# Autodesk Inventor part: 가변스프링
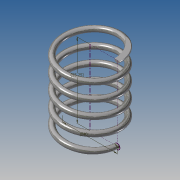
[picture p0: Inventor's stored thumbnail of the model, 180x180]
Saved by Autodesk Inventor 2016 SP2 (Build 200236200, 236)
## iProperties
Created: 2019-03
Part Number: 가변스프링
Material: 스테인레스 스틸
Document SubType Name: Modeling
Designer: EZ
Density: 8 g/cm^3
Appearance: 반연마
Mass: 62.1952 g
Surface Area: 78.8408 cm^2
Volume: 7.7744 cm^3
Author: EZ
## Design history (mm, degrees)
sketch "스케치1"
  geometry: L1 (0, 0)-(20, 0); L2 (20, 0)-(20, 55.251); L3 (20, 55.251)-(0, 55.251); L4 (0, 55.251)-(0, 0); C1 r 2 at (20, 0)
  constraints: 8 end point, 2 parallel, 1 centre point, 1 coincident, 1 horizontal, 1 perpendicular
  dimensions: "d0" = 4 diameter of C1; "d2" = 40 diameter of L2 L4; "d16" = 55.2509 distance between parallel lines of L1 L3 (derived)
feature "코일1" sketch "스케치1" pitch "d4" = 10; turns "d6" = 5; dims "d5" = 55.25091 (= d3), "d7" = 0, angle "d8" = 90 deg, angle "d9" = 90 deg, "d10" = 0, "d11" = 0
sketch "스케치2"
  geometry: L1 (-18, 0)-(-22, 0) reference
  constraints: 1 horizontal alignment
extrude "돌출1" cut sketch "스케치2" stored distance "d12" = 10; taper "d13" = 0 deg
node "작업 평면1"
sketch "스케치3"
  geometry: L1 (-2, 0)-(2, 0) reference
  constraints: 1 horizontal alignment
extrude "돌출2" cut sketch "스케치3" stored distance "d14" = 10; taper "d15" = 0 deg
node "솔리드1"
node "절단 모서리 투영1"
node "절단 모서리 투영2"
other parameters: "d3" = 55.25091 (derived)
